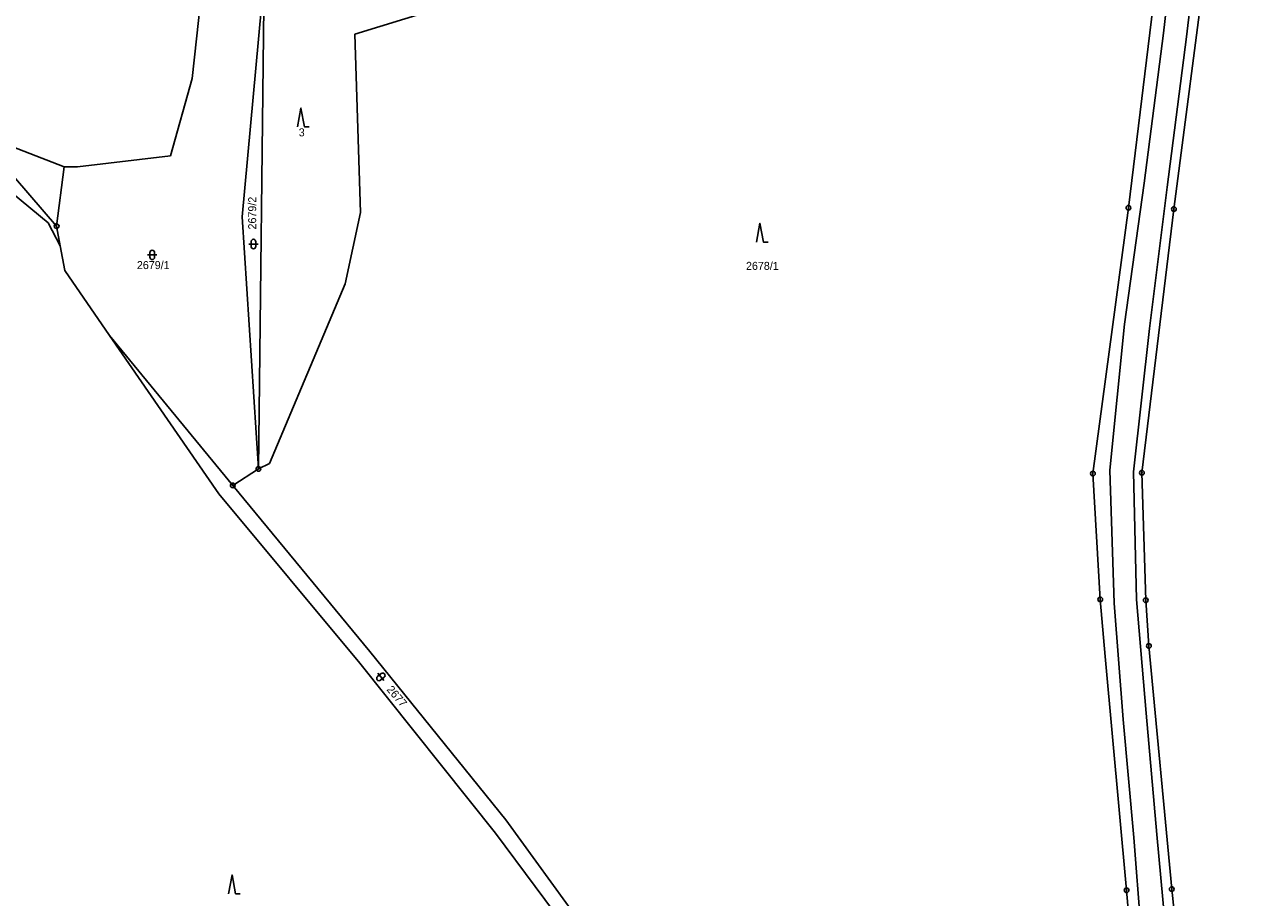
# Model space of a CAD drawing. Extents: x -736345 to -729997, y -1130177 to -1122501.
# Drawn here: x -734447.9 to -734189.8, y -1125466.6 to -1125281.1 of the extents above; entities that cross this region are included whole.
import ezdxf

# ---------------------------------------------------------------- set-up
doc = ezdxf.new("R2010")
doc.units = 0
for name, color, linetype in [('Vrstva 1', 7, 'Continuous'), ('Vrstva 18', 7, 'Continuous'), ('Vrstva 25', 7, 'Continuous'), ('Vrstva 4', 7, 'Continuous')]:
    doc.layers.add(name, color=color, linetype=linetype)

msp = doc.modelspace()

# ---------------------------------------------------------------- linework, layer by layer
at = {"layer": 'Vrstva 1'}
for points in [[(-734189.83, -1125212.7), (-734203.8, -1125320.34)], [(-734201.21, -1125219.6), (-734213.46, -1125320.08)], [(-734409.03, -1125262.72), (-734412.27, -1125292.63)], [(-734401.69, -1125322.03), (-734396.98, -1125271.09)], [(-734396.98, -1125271.09), (-734398.24, -1125375.52)], [(-734377.74, -1125283.23), (-734361.82, -1125278.34)], [(-734376.56, -1125321.09), (-734377.74, -1125283.23)], [(-734412.27, -1125292.63), (-734416.88, -1125309.06)], [(-734439.5, -1125311.38), (-734455.42, -1125305.2)], [(-734463.03, -1125306.64), (-734442.9, -1125323.28)], [(-734441.08, -1125323.96), (-734452.85, -1125310.29)], [(-734436.64, -1125311.36), (-734439.5, -1125311.38)], [(-734416.88, -1125309.06), (-734436.64, -1125311.36)], [(-734439.5, -1125311.38), (-734441.08, -1125323.96)], [(-734379.79, -1125336.24), (-734376.56, -1125321.09)], [(-734221, -1125376.5), (-734213.46, -1125320.08)], [(-734203.8, -1125320.34), (-734210.6, -1125376.34)], [(-734442.9, -1125323.28), (-734440.31, -1125328.15)], [(-734440.31, -1125328.15), (-734441.08, -1125323.96)], [(-734398.24, -1125375.52), (-734401.69, -1125322.03)], [(-734440.31, -1125328.15), (-734439.35, -1125333.36)], [(-734439.35, -1125333.36), (-734429.87, -1125347.21)], [(-734395.88, -1125374.35), (-734379.79, -1125336.24)], [(-734403.68, -1125379.04), (-734429.87, -1125347.21)], [(-734429.87, -1125347.21), (-734406.64, -1125380.8)], [(-734398.24, -1125375.52), (-734403.68, -1125379.04)], [(-734398.24, -1125375.52), (-734395.88, -1125374.35)], [(-734219.45, -1125403.23), (-734221, -1125376.5)], [(-734209.77, -1125403.41), (-734210.6, -1125376.34)], [(-734406.64, -1125380.8), (-734376.71, -1125416.75)], [(-734374.54, -1125414.31), (-734403.68, -1125379.04)], [(-734218.41, -1125415.36), (-734219.45, -1125403.23)], [(-734209.12, -1125413.12), (-734209.77, -1125403.41)], [(-734345.68, -1125450.03), (-734374.54, -1125414.31)], [(-734209.12, -1125413.12), (-734204.27, -1125464.75)], [(-734376.71, -1125416.75), (-734347.89, -1125452.87)], [(-734213.84, -1125465), (-734218.41, -1125415.36)], [(-734320.22, -1125485.15), (-734345.68, -1125450.03)], [(-734347.89, -1125452.87), (-734322.58, -1125486.81)], [(-734212.55, -1125480.54), (-734213.84, -1125465)], [(-734204.27, -1125464.75), (-734201.96, -1125486.52)]]:
    msp.add_lwpolyline(points, dxfattribs=at)
at = {"layer": 'Vrstva 25'}
for points in [[(-734389.94, -1125302.91), (-734389.19, -1125298.91), (-734388.44, -1125302.91), (-734387.44, -1125302.91)], [(-734292.48, -1125327.36), (-734291.73, -1125323.36), (-734290.98, -1125327.36), (-734289.98, -1125327.36)], [(-734400.29, -1125327.77), (-734398.29, -1125327.77)], [(-734399.79, -1125328.27), (-734399.79, -1125327.27)], [(-734398.79, -1125327.27), (-734398.79, -1125328.27)], [(-734421.78, -1125330.09), (-734419.78, -1125330.09)], [(-734421.28, -1125330.59), (-734421.28, -1125329.59)], [(-734420.28, -1125329.59), (-734420.28, -1125330.59)], [(-734372.928, -1125419.61), (-734372.153, -1125418.979)], [(-734371.592, -1125420.456), (-734372.856, -1125418.908)], [(-734371.521, -1125419.753), (-734372.296, -1125420.385)], [(-734404.57, -1125465.75), (-734403.82, -1125461.75), (-734403.07, -1125465.75), (-734402.07, -1125465.75)]]:
    msp.add_lwpolyline(points, dxfattribs=at)
for centre, radius in [((-734213.46, -1125320.08), 0.5), ((-734213.46, -1125320.08), 0.032), ((-734203.8, -1125320.34), 0.5), ((-734203.8, -1125320.34), 0.032), ((-734441.08, -1125323.96), 0.5), ((-734441.08, -1125323.96), 0.032), ((-734398.24, -1125375.52), 0.5), ((-734398.24, -1125375.52), 0.032), ((-734210.6, -1125376.34), 0.5), ((-734221, -1125376.5), 0.5), ((-734221, -1125376.5), 0.032), ((-734210.6, -1125376.34), 0.032), ((-734403.68, -1125379.04), 0.5), ((-734403.68, -1125379.04), 0.032), ((-734219.45, -1125403.23), 0.5), ((-734219.45, -1125403.23), 0.032), ((-734209.77, -1125403.41), 0.5), ((-734209.77, -1125403.41), 0.032), ((-734209.12, -1125413.12), 0.5), ((-734209.12, -1125413.12), 0.032), ((-734213.84, -1125465), 0.5), ((-734213.84, -1125465), 0.032), ((-734204.27, -1125464.75), 0.5), ((-734204.27, -1125464.75), 0.032)]:
    msp.add_circle(centre, radius, dxfattribs=at)
for centre, start, end in [((-734399.29, -1125327.27), 0.10099, 180.00143), ((-734420.78, -1125329.59), 0.10099, 180.00143), ((-734399.29, -1125328.27), 180.10243, 0.00286), ((-734420.78, -1125330.59), 180.10243, 0.00286), ((-734372.612, -1125419.997), 129.37659, 309.16297), ((-734371.837, -1125419.366), 309.33352, 129.23395)]:
    msp.add_arc(centre, 0.5, start, end, dxfattribs=at)
at = {"layer": 'Vrstva 4'}
for points in [[(-734202.04, -1125248.24), (-734206.02, -1125283)], [(-734201.14, -1125283.76), (-734196.92, -1125248.35)], [(-734206.02, -1125283), (-734210.11, -1125314.86)], [(-734205.22, -1125315.67), (-734201.14, -1125283.76)], [(-734210.11, -1125314.86), (-734214.28, -1125344.8)], [(-734209.02, -1125345.69), (-734205.22, -1125315.67)], [(-734214.28, -1125344.8), (-734217.38, -1125375.76)], [(-734212.4, -1125376.12), (-734209.02, -1125345.69)], [(-734217.38, -1125375.76), (-734216.48, -1125404)], [(-734211.74, -1125403.24), (-734212.4, -1125376.12)], [(-734216.48, -1125404), (-734214.57, -1125428.7)], [(-734209.67, -1125427.42), (-734211.74, -1125403.24)], [(-734207.44, -1125453.16), (-734209.67, -1125427.42)], [(-734212.31, -1125453.8), (-734214.57, -1125428.7)], [(-734202.44, -1125506.82), (-734207.44, -1125453.16)], [(-734209.36, -1125492.26), (-734212.31, -1125453.8)]]:
    msp.add_lwpolyline(points, dxfattribs=at)

# ---------------------------------------------------------------- texts
at = {"layer": 'Vrstva 18'}
for s, p in [('3', (-734389.67, -1125304.91)), ('2679/1', (-734424.04, -1125333.09)), ('2678/1', (-734294.68, -1125333.26))]:
    msp.add_text(s, height=1.7, dxfattribs=at).set_placement(p)
for s, rotation, p in [('2679/2', 90.00072, (-734398.7, -1125324.68)), ('2677', 310.60247, (-734371.108, -1125422.431))]:
    msp.add_text(s, height=1.7, rotation=rotation, dxfattribs=at).set_placement(p)

doc.saveas('drawing.dxf')
